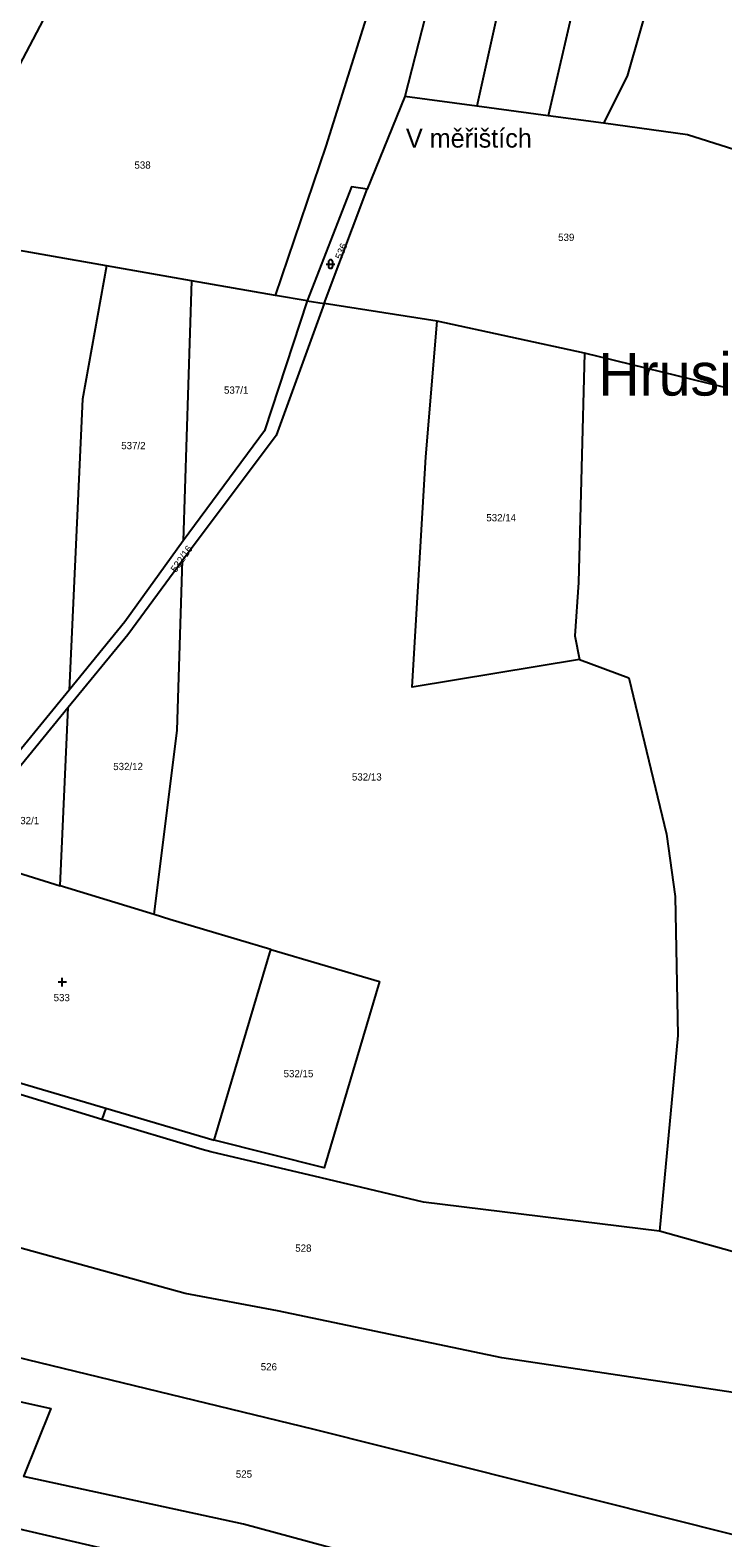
# Model space of a CAD drawing. Extents: x -725728 to -720881, y -1068679 to -1063504.
# Drawn here: x -722824.4 to -722662.5, y -1065371.2 to -1065018.4 of the extents above; entities that cross this region are included whole.
import ezdxf

# ---------------------------------------------------------------- set-up
doc = ezdxf.new("R2010")
doc.units = 0
for name, color, linetype in [('Hranice parcel', 7, 'Continuous'), ('Parcelní čísla', 7, 'Continuous'), ('Pop  PČ popisy', 7, 'Continuous'), ('Značky kultur', 7, 'Continuous')]:
    doc.layers.add(name, color=color, linetype=linetype)

# ---------------------------------------------------------------- blocks, each defined once
blk = doc.blocks.new('3.15')
at = {"layer": 'Značky kultur'}
for p, q in [((0.1, 0.1), (-0.1, 0.1)), ((0, 0), (0, 0.2))]:
    blk.add_line(p, q, dxfattribs=at)
blk = doc.blocks.new('3.16_2')
at = {"layer": 'Značky kultur'}
for p, q in [((-0.1, 0.1), (0.1, 0.1)), ((-0.05, 0.15), (-0.05, 0.05)), ((0.05, 0.05), (0.05, 0.15))]:
    blk.add_line(p, q, dxfattribs=at)
for centre, start, end in [((0, 0.15), 0, 180), ((0, 0.05), 180, 359.9879)]:
    blk.add_arc(centre, 0.05, start, end, dxfattribs=at)

msp = doc.modelspace()

# ---------------------------------------------------------------- linework, layer by layer
at = {"layer": 'Hranice parcel'}
for p, q in [((-722736.8, -1065033.92), (-722745.61, -1065055.6)), ((-722719.95, -1065036.2), (-722736.8, -1065033.92)), ((-722703.33, -1065038.45), (-722719.95, -1065036.2)), ((-722690.39, -1065040.2), (-722703.33, -1065038.45)), ((-722755.68, -1065082.32), (-722745.61, -1065055.6)), ((-722786.68, -1065077.05), (-722806.52, -1065073.55)), ((-722786.68, -1065077.05), (-722788.62, -1065137.87)), ((-722767.04, -1065080.51), (-722786.68, -1065077.05)), ((-722759.61, -1065081.7), (-722767.04, -1065080.51)), ((-722759.61, -1065081.7), (-722755.68, -1065082.32)), ((-722729.22, -1065086.52), (-722755.68, -1065082.32)), ((-722694.77, -1065093.95), (-722729.22, -1065086.52)), ((-722662.29, -1065101.97), (-722694.77, -1065093.95)), ((-722815.3, -1065172.83), (-722834.24, -1065195.98)), ((-722815.49, -1065176.9), (-722835.07, -1065200.8)), ((-722817.41, -1065218.57), (-722815.49, -1065176.9)), ((-722837.07, -1065212.51), (-722817.41, -1065218.57)), ((-722795.44, -1065225.34), (-722817.41, -1065218.57)), ((-722781.39, -1065278.11), (-722768.15, -1065233.47)), ((-722807.63, -1065273.24), (-722854.71, -1065258.99)), ((-722851.77, -1065257.4), (-722806.74, -1065270.59)), ((-722806.74, -1065270.59), (-722807.63, -1065273.24)), ((-722806.74, -1065270.59), (-722781.39, -1065278.11)), ((-722649.97, -1065307.09), (-722677.3, -1065299.38))]:
    msp.add_line(p, q, dxfattribs=at)
for points in [[(-722674.68, -1064822.33), (-722680.33, -1064846.53), (-722695.76, -1064881.7), (-722711.63, -1064937.75), (-722723.21, -1064980.57), (-722736.8, -1065033.92)], [(-722675.5, -1064879.08), (-722706.77, -1064975.85), (-722715.61, -1065016.51), (-722719.95, -1065036.2)], [(-722664.94, -1064890.97), (-722679.91, -1064948.1), (-722688.74, -1064975.32), (-722703.33, -1065038.45)], [(-722664.94, -1064890.97), (-722662.94, -1064903.42), (-722663.69, -1064931.5), (-722672.66, -1064986.69), (-722684.85, -1065029.13), (-722690.39, -1065040.2)], [(-722846.3, -1065069.9), (-722843.53, -1065058.25), (-722816.53, -1065006.87)], [(-722767.04, -1065080.51), (-722755.2, -1065045.51), (-722743.16, -1065007.28)], [(-722645.89, -1065050.76), (-722670.73, -1065042.86), (-722690.39, -1065040.2)], [(-722745.61, -1065055.6), (-722749.25, -1065055.08), (-722759.61, -1065081.7)], [(-722806.52, -1065073.55), (-722832.72, -1065068.93), (-722846.3, -1065069.9)], [(-722806.52, -1065073.55), (-722812.15, -1065104.72), (-722815.3, -1065172.83)], [(-722755.68, -1065082.32), (-722766.89, -1065113.24), (-722788.77, -1065142.51)], [(-722759.61, -1065081.7), (-722769.61, -1065112.14), (-722788.62, -1065137.87)], [(-722695.97, -1065165.68), (-722735.07, -1065172.11), (-722731.91, -1065118.23), (-722729.22, -1065086.52)], [(-722694.77, -1065093.95), (-722696.22, -1065147.63), (-722697.1, -1065160.13), (-722695.97, -1065165.68)], [(-722788.62, -1065137.87), (-722802.23, -1065156.86), (-722815.3, -1065172.83)], [(-722788.77, -1065142.51), (-722801.57, -1065159.91), (-722815.49, -1065176.9)], [(-722795.44, -1065225.34), (-722790.03, -1065182.19), (-722788.77, -1065142.51)], [(-722695.97, -1065165.68), (-722684.48, -1065169.95), (-722675.63, -1065206.54), (-722673.63, -1065221.12), (-722672.98, -1065253.6), (-722677.3, -1065299.38)], [(-722768.15, -1065233.47), (-722791.73, -1065226.48), (-722795.44, -1065225.34)], [(-722768.15, -1065233.47), (-722742.73, -1065241.01), (-722755.65, -1065284.56), (-722781.39, -1065278.11)], [(-722677.3, -1065299.38), (-722732.46, -1065292.65), (-722756.36, -1065286.96), (-722782.19, -1065280.81), (-722784.2, -1065280.33), (-722807.63, -1065273.24)], [(-722643.95, -1065339.55), (-722714.15, -1065329.03), (-722766.59, -1065318.05), (-722788.2, -1065314.02), (-722874.06, -1065290.3)], [(-722643.2, -1065374.7), (-722758.04, -1065345.82), (-722883.74, -1065315.27)], [(-722887.82, -1065326.02), (-722853.2, -1065333.42), (-722819.58, -1065340.93), (-722825.96, -1065356.83)], [(-722662.65, -1065398.33), (-722774.56, -1065367.94), (-722825.96, -1065356.83)], [(-722672.9, -1065410.84), (-722781.31, -1065379.75), (-722830.56, -1065368.3)]]:
    msp.add_lwpolyline(points, dxfattribs=at)

# ---------------------------------------------------------------- block references
at = {"layer": 'Značky kultur', "xscale": 10, "yscale": 10}
for name, p in [('3.16_2', (-722754.17, -1065074.12)), ('3.15', (-722816.88, -1065242.14))]:
    msp.add_blockref(name, p, dxfattribs=at)

# ---------------------------------------------------------------- texts
at = {"layer": 'Parcelní čísla'}
for s, p in [('538', (-722800.02, -1065050.81)), ('539', (-722700.97, -1065067.72)), ('537/1', (-722779.08, -1065103.47)), ('537/2', (-722803.11, -1065116.45)), ('532/14', (-722717.76, -1065133.32)), ('532/12', (-722804.98, -1065191.53)), ('532/13', (-722749.18, -1065193.97)), ('532/1', (-722827.98, -1065204.18)), ('533', (-722818.91, -1065245.6)), ('532/15', (-722765.15, -1065263.39)), ('528', (-722762.43, -1065304.22)), ('526', (-722770.49, -1065331.98)), ('525', (-722776.32, -1065357.08))]:
    msp.add_text(s, height=1.7, dxfattribs=at).set_placement(p)
for s, rotation, p in [('536', 68, (-722751.61, -1065072.19)), ('532/16', 55, (-722790.31, -1065145.44))]:
    msp.add_text(s, height=1.7, rotation=rotation, dxfattribs=at).set_placement(p)
at = {"layer": 'Pop  PČ popisy'}
for s, height, p in [('V měřištích', 4.4, (-722736.55, -1065045.88)), ('Hrusice 648655', 10, (-722691.57, -1065103.9))]:
    msp.add_text(s, height=height, dxfattribs=at).set_placement(p)

doc.saveas('drawing.dxf')
